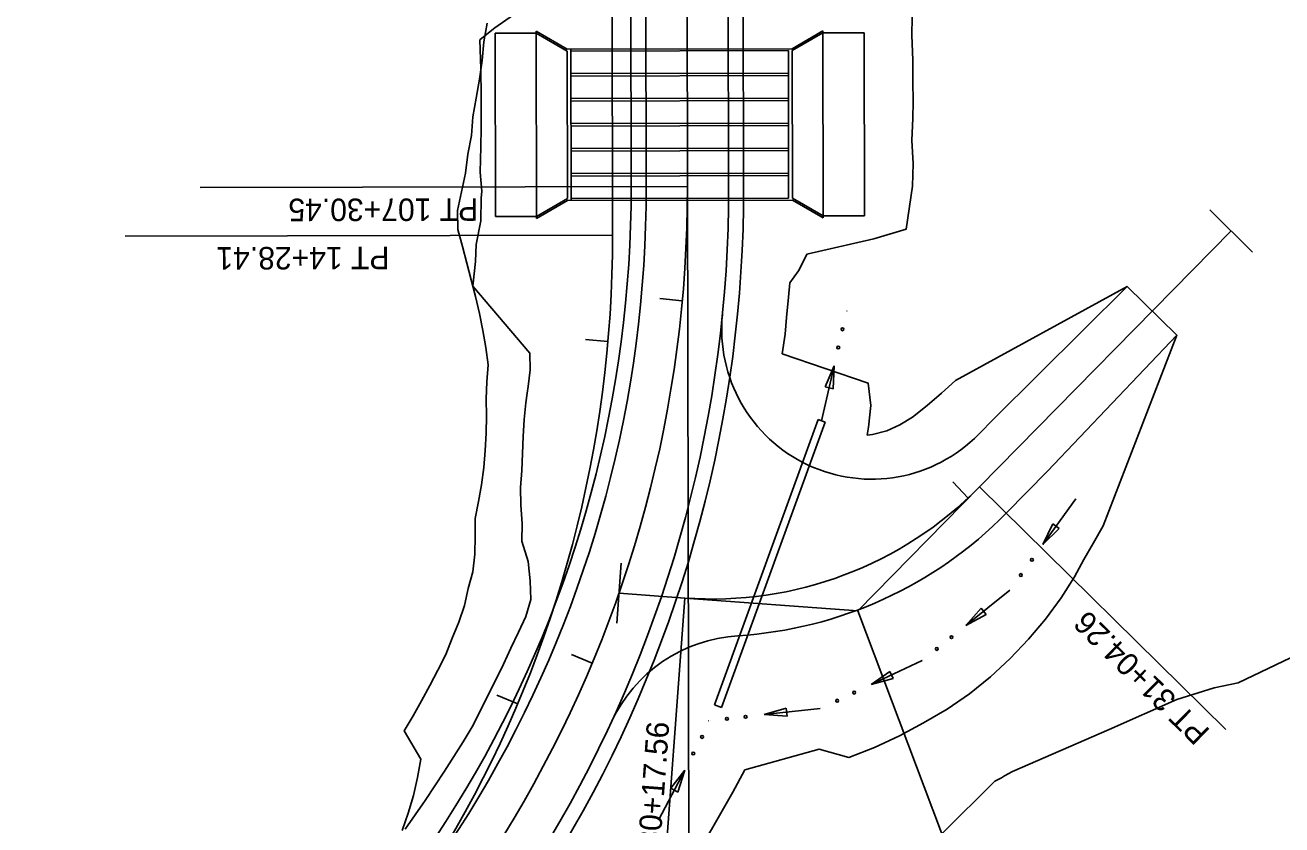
# Model space of a CAD drawing. Extents: x 1395202 to 1465904, y 1787951 to 1846942.
# Drawn here: x 1405603.4 to 1405938.6, y 1842358 to 1842571.2 of the extents above; entities that cross this region are included whole.
import ezdxf

# ---------------------------------------------------------------- set-up
doc = ezdxf.new("R2010")
doc.units = 0
for name, color, linetype in [('R_Drainage', 7, 'Continuous'), ('R_Horiz Alg Tangents', 7, 'Continuous'), ('R_Horz Alg', 7, 'Continuous'), ('R_Horz Alg Annot', 7, 'Continuous'), ('R_Horz Alg Stationing', 7, 'Continuous'), ('R_Perimeter', 7, 'Continuous'), ('R_Proposed Lane', 7, 'Continuous'), ('R_Proposed Shoulder', 7, 'Continuous'), ('R_SFHA', 7, 'Continuous'), ('R_Special Ditch', 7, 'Continuous'), ('R_Temp Perimeter', 7, 'Continuous'), ('R_Temp_Horz Alg', 7, 'Continuous'), ('R_Temp_Horz Alg Annot', 7, 'Continuous'), ('R_Temp_Horz Alg Stationing', 7, 'Continuous')]:
    doc.layers.add(name, color=color, linetype=linetype)

msp = doc.modelspace()

# ---------------------------------------------------------------- linework, layer by layer
at = {"layer": 'R_Drainage'}
for p, q in [((1405728.78, 1842569.06), (1405739.78, 1842569.08)), ((1405728.86, 1842520.19), (1405728.78, 1842569.06)), ((1405739.78, 1842569.58), (1405748, 1842564.81)), ((1405739.78, 1842569.58), (1405739.78, 1842569.08)), ((1405739.78, 1842569.08), (1405748, 1842564.31)), ((1405739.78, 1842569.08), (1405739.86, 1842520.21)), ((1405808, 1842564.93), (1405816.24, 1842569.67)), ((1405808, 1842564.43), (1405816.24, 1842569.17)), ((1405816.24, 1842569.67), (1405816.24, 1842569.17)), ((1405816.24, 1842569.17), (1405827.24, 1842569.19)), ((1405816.32, 1842520.37), (1405816.24, 1842569.17)), ((1405827.24, 1842569.19), (1405827.32, 1842520.39)), ((1405748, 1842564.81), (1405808, 1842564.93)), ((1405748, 1842564.31), (1405748.08, 1842524.98)), ((1405749.08, 1842524.48), (1405749, 1842564.81)), ((1405749, 1842564.31), (1405807, 1842564.43)), ((1405807, 1842564.43), (1405807.08, 1842525.1)), ((1405808, 1842564.43), (1405808.08, 1842525.1)), ((1405749.01, 1842558.31), (1405807.01, 1842558.43)), ((1405749.02, 1842557.65), (1405807.01, 1842557.77)), ((1405749.03, 1842551.65), (1405807.03, 1842551.77)), ((1405749.03, 1842550.98), (1405807.03, 1842551.1)), ((1405749.04, 1842544.98), (1405807.04, 1842545.1)), ((1405749.04, 1842544.31), (1405807.04, 1842544.43)), ((1405749.05, 1842538.31), (1405807.05, 1842538.43)), ((1405749.06, 1842537.65), (1405807.06, 1842537.77)), ((1405749.07, 1842531.65), (1405807.07, 1842531.77)), ((1405749.07, 1842530.98), (1405807.07, 1842531.1)), ((1405739.86, 1842520.21), (1405748.08, 1842524.98)), ((1405749.08, 1842524.98), (1405807.08, 1842525.1)), ((1405808.08, 1842525.1), (1405816.32, 1842520.37)), ((1405739.87, 1842519.71), (1405748.08, 1842524.48)), ((1405748.08, 1842524.48), (1405808.08, 1842524.6)), ((1405808.08, 1842524.6), (1405816.32, 1842519.87)), ((1405739.86, 1842520.21), (1405728.86, 1842520.19)), ((1405739.87, 1842519.71), (1405739.86, 1842520.21)), ((1405827.32, 1842520.39), (1405816.32, 1842520.37)), ((1405816.32, 1842519.87), (1405816.32, 1842520.37)), ((1405787.26, 1842389.96), (1405814.97, 1842466.07)), ((1405816.85, 1842465.38), (1405789.14, 1842389.27)), ((1405814.97, 1842466.07), (1405816.85, 1842465.38)), ((1405787.26, 1842389.96), (1405789.14, 1842389.27))]:
    msp.add_line(p, q, dxfattribs=at)
at = {"layer": 'R_Horiz Alg Tangents'}
for p, q in [((1405780.46, 1842339.07), (1405780.08, 1842528.16)), ((1405825.52, 1842415.08), (1405857.98, 1842448.08)), ((1405779.36, 1842418.47), (1405825.52, 1842415.08))]:
    msp.add_line(p, q, dxfattribs=at)
at = {"layer": 'R_Horz Alg'}
for p, q in [((1405780.08, 1842528.16), (1405779.12, 1842997.71)), ((1405780.08, 1842528.16), (1405779.12, 1842997.71)), ((1405857.98, 1842448.08), (1405925.1, 1842516.34)), ((1405761.84, 1842419.76), (1405779.36, 1842418.47))]:
    msp.add_line(p, q, dxfattribs=at)
for centre, radius, start, end in [((1405452.67, 1842527.5), 327.4, 300.1, 0.1167), ((1405452.67, 1842527.5), 327.4, 300.1, 0.1167), ((1405786.68, 1842518.2), 100, 265.8008, 315.4775)]:
    msp.add_arc(centre, radius, start, end, dxfattribs=at)
at = {"layer": 'R_Horz Alg Annot'}
msp.add_line((1405780.08, 1842528.16), (1405780.46, 1842339.07), dxfattribs=at)
for points in [[(1405780.08, 1842528.16), (1405650.08, 1842527.9)], [(1405923.71, 1842383.43), (1405857.98, 1842448.08)], [(1405773.28, 1842335.74), (1405779.36, 1842418.47)], [(1405825.52, 1842415.08), (1405867.82, 1842302.78)]]:
    msp.add_lwpolyline(points, dxfattribs=at)
at = {"layer": 'R_Horz Alg Stationing'}
for points in [[(1405919.4, 1842521.95), (1405930.81, 1842510.73)], [(1405919.4, 1842521.95), (1405930.81, 1842510.73)], [(1405772.75, 1842498.3), (1405778.72, 1842497.75)], [(1405850.83, 1842449.49), (1405854.92, 1842445.11)], [(1405762.43, 1842427.74), (1405761.26, 1842411.78)], [(1405749.15, 1842403.4), (1405754.69, 1842401.08)]]:
    msp.add_lwpolyline(points, dxfattribs=at)
at = {"layer": 'R_Perimeter'}
for points in [[(1405704.84, 1842356.85), (1405707.48, 1842360.67), (1405710.1, 1842364.52), (1405712.69, 1842368.39), (1405715.26, 1842372.28), (1405717.79, 1842376.2), (1405720.3, 1842380.14), (1405722.65, 1842384.17), (1405724.79, 1842388.32), (1405726.89, 1842392.49), (1405728.96, 1842396.67), (1405731, 1842400.88), (1405733.01, 1842405.09), (1405734.99, 1842409.33), (1405736.94, 1842413.58), (1405738.32, 1842418.06), (1405738.16, 1842423.09), (1405737.62, 1842428.2), (1405735.94, 1842433.61), (1405735.97, 1842438.38), (1405735.68, 1842443.2), (1405735.53, 1842447.92), (1405735.88, 1842452.47), (1405736.13, 1842457.02), (1405736.28, 1842461.56), (1405736.52, 1842466.06), (1405737.02, 1842470.48), (1405737.36, 1842473.08), (1405737.6, 1842474.88), (1405738.15, 1842479.28), (1405738.07, 1842483.76), (1405738.07, 1842483.76), (1405738.07, 1842483.76), (1405738.07, 1842483.76), (1405738.07, 1842483.76), (1405722.84, 1842501.66), (1405723.58, 1842508.22), (1405723.58, 1842508.22), (1405723.58, 1842508.22), (1405723.58, 1842508.22), (1405723.58, 1842508.22), (1405723.73, 1842512.73), (1405724.94, 1842519.05), (1405725.06, 1842525.05), (1405725.22, 1842526.95), (1405724.83, 1842532.01), (1405724.99, 1842538.75), (1405724.99, 1842539.03), (1405725.08, 1842543.47), (1405725.04, 1842547.56), (1405725.07, 1842552.28), (1405725.01, 1842559.6), (1405724.75, 1842567.34), (1405724.81, 1842567.43), (1405728.74, 1842570.53), (1405733.71, 1842573.99)], [(1405840.05, 1842573.34), (1405839.93, 1842568.52), (1405840.18, 1842561.91), (1405840.18, 1842555.94), (1405840.25, 1842551.13), (1405840.31, 1842550.85), (1405840.18, 1842546.4), (1405839.93, 1842540.43), (1405840.31, 1842534.33), (1405840.08, 1842528.29), (1405838.4, 1842516.8), (1405829.84, 1842514.28), (1405811.9, 1842510.13), (1405811.9, 1842510.09), (1405809.7, 1842505.73), (1405807.37, 1842502.53), (1405807.01, 1842498.69), (1405806.49, 1842493.26), (1405806.11, 1842488.87), (1405805.36, 1842483.61), (1405828.25, 1842475.8), (1405829.03, 1842469.82), (1405828.4, 1842464.03), (1405828.04, 1842461.89)], [(1405828.04, 1842461.89), (1405829.44, 1842462.08), (1405833.24, 1842463.05), (1405836.72, 1842464.61), (1405840.1, 1842466.7), (1405844.03, 1842469.84), (1405847.86, 1842473.09), (1405851.55, 1842476.48), (1405897.35, 1842501.55), (1405910.61, 1842488.52), (1405890.96, 1842437.71), (1405888.39, 1842433.23), (1405885.85, 1842428.71), (1405883.36, 1842424.15), (1405879.73, 1842418.53), (1405875.58, 1842412.88), (1405871.05, 1842407.47), (1405866.14, 1842402.33), (1405860.89, 1842397.45), (1405855.29, 1842392.93), (1405849.32, 1842388.88), (1405843.07, 1842385.22), (1405836.65, 1842381.76), (1405830.02, 1842378.64), (1405823.16, 1842375.97), (1405815.21, 1842378.21), (1405795.43, 1842372.67)], [(1405795.43, 1842372.67), (1405792.23, 1842366.72), (1405789.39, 1842361.72), (1405786.53, 1842356.75), (1405783.6, 1842351.82), (1405780.37, 1842347.06), (1405776.85, 1842342.5), (1405773.55, 1842337.82), (1405770.06, 1842333.29), (1405766.44, 1842328.85), (1405762.82, 1842324.45), (1405759.31, 1842319.99), (1405756.04, 1842315.37), (1405752.92, 1842310.65), (1405754.04, 1842302.76), (1405750.24, 1842298.44), (1405746.69, 1842293.94), (1405743.16, 1842289.42), (1405738.65, 1842285.06)]]:
    msp.add_lwpolyline(points, dxfattribs=at)
at = {"layer": 'R_Proposed Lane'}
for p, q in [((1405769.08, 1842528.24), (1405768.53, 1842797.69)), ((1405791.07, 1842528.28), (1405790.53, 1842797.73)), ((1405897.35, 1842501.55), (1405861.88, 1842466.31)), ((1405910.61, 1842488.52), (1405876.14, 1842452.29)), ((1405861.88, 1842466.31), (1405857.75, 1842462.11)), ((1405876.14, 1842452.29), (1405865.11, 1842441.07))]:
    msp.add_line(p, q, dxfattribs=at)
for centre, radius, start, end in [((1405452.67, 1842527.5), 316.4, 300.1, 0.1338), ((1405452.67, 1842527.5), 338.4, 300.1, 0.1338), ((1405829.23, 1842490.16), 40, 174.3376, 315.4775), ((1405786.68, 1842518.2), 110, 273.5817, 315.4775), ((1405796.05, 1842368.5), 40, 93.5817, 155.1535)]:
    msp.add_arc(centre, radius, start, end, dxfattribs=at)
at = {"layer": 'R_Proposed Shoulder'}
for p, q in [((1405765.08, 1842528.23), (1405764.53, 1842797.68)), ((1405795.07, 1842528.29), (1405794.53, 1842797.74))]:
    msp.add_line(p, q, dxfattribs=at)
for radius in [312.4, 342.4]:
    msp.add_arc((1405452.67, 1842527.5), radius, 300.1, 0.1338, dxfattribs=at)
at = {"layer": 'R_SFHA'}
msp.add_lwpolyline([(1405942.98, 1842403.54), (1405926.95, 1842395.84), (1405920.59, 1842394.5), (1405910.58, 1842391.39), (1405892.6, 1842383.39), (1405866.75, 1842372.19), (1405864.61, 1842371.04), (1405863.87, 1842370.51), (1405862.03, 1842369.6), (1405848.1, 1842355.77)], dxfattribs=at)
at = {"layer": 'R_Special Ditch'}
for p, q in [((1405822.59, 1842494.98), (1405822.6, 1842495.01)), ((1405819.24, 1842480.36), (1405815.88, 1842465.74)), ((1405819.24, 1842480.36), (1405816.86, 1842474.75)), ((1405818.93, 1842474.27), (1405819.24, 1842480.36)), ((1405816.86, 1842474.75), (1405818.93, 1842474.27)), ((1405874.86, 1842432.75), (1405883.64, 1842444.91)), ((1405877.52, 1842438.23), (1405874.86, 1842432.75)), ((1405879.23, 1842437), (1405877.52, 1842438.23)), ((1405874.86, 1842432.75), (1405879.23, 1842437)), ((1405854.38, 1842411.18), (1405866.08, 1842420.57)), ((1405866.09, 1842420.58), (1405866.07, 1842420.55)), ((1405858.4, 1842415.76), (1405854.38, 1842411.18)), ((1405859.72, 1842414.11), (1405858.4, 1842415.76)), ((1405854.38, 1842411.18), (1405859.72, 1842414.11)), ((1405829.09, 1842395.4), (1405842.66, 1842401.79)), ((1405842.67, 1842401.8), (1405842.64, 1842401.78)), ((1405834.07, 1842398.91), (1405829.09, 1842395.4)), ((1405834.97, 1842397), (1405834.07, 1842398.91)), ((1405829.09, 1842395.4), (1405834.97, 1842397)), ((1405806.44, 1842389.09), (1405800.59, 1842387.39)), ((1405800.59, 1842387.39), (1405815.5, 1842389.01)), ((1405800.59, 1842387.39), (1405806.66, 1842386.98)), ((1405806.66, 1842386.98), (1405806.44, 1842389.09)), ((1405815.52, 1842389.01), (1405815.48, 1842389)), ((1405785.67, 1842385.77), (1405785.64, 1842385.77)), ((1405786.33, 1842385.83), (1405786.35, 1842385.86)), ((1405779.36, 1842372.55), (1405772.38, 1842359.27)), ((1405779.36, 1842372.55), (1405775.63, 1842367.73)), ((1405777.5, 1842366.74), (1405779.36, 1842372.55)), ((1405775.63, 1842367.73), (1405777.5, 1842366.74)), ((1405772.47, 1842359.41), (1405772.49, 1842359.45))]:
    msp.add_line(p, q, dxfattribs=at)
for centre in [(1405821.44, 1842490.13), (1405820.32, 1842485.25), (1405871.97, 1842428.67), (1405869.03, 1842424.6), (1405850.49, 1842408.02), (1405846.58, 1842404.89), (1405820.04, 1842391.1), (1405824.57, 1842393.24), (1405790.63, 1842386.27), (1405795.61, 1842386.81), (1405783.98, 1842381.43), (1405781.65, 1842377)]:
    msp.add_circle(centre, 0.375, dxfattribs=at)
at = {"layer": 'R_Temp Perimeter'}
msp.add_lwpolyline([(1405703.97, 1842356.48), (1405705.64, 1842361.07), (1405707.01, 1842365.8), (1405708.13, 1842370.63), (1405709, 1842375.54), (1405704.5, 1842383.08), (1405706.89, 1842387.06), (1405709.2, 1842391.07), (1405711.39, 1842395.17), (1405713.55, 1842399.28), (1405715.61, 1842403.45), (1405717.35, 1842407.75), (1405719.12, 1842412.05), (1405720.64, 1842416.44), (1405721.59, 1842421.02), (1405722.81, 1842425.49), (1405723.35, 1842430.16), (1405723.45, 1842434.93), (1405723.49, 1842439.68), (1405724.38, 1842444.18), (1405725.16, 1842448.69), (1405725.76, 1842453.24), (1405726.18, 1842457.81), (1405726.44, 1842462.39), (1405726.52, 1842466.99), (1405726.42, 1842471.59), (1405726.59, 1842476.13), (1405726.95, 1842480.63), (1405726.34, 1842485.23), (1405725.53, 1842489.81), (1405724.6, 1842494.36), (1405723.55, 1842498.88), (1405722.41, 1842503.36), (1405721.26, 1842507.8), (1405720.08, 1842512.21), (1405718.86, 1842516.77), (1405718.76, 1842521.77), (1405719.83, 1842526.78), (1405720.86, 1842531.78), (1405721.47, 1842536.78), (1405722.51, 1842541.78), (1405722.88, 1842546.78), (1405723.72, 1842551.78), (1405724.62, 1842556.79), (1405725.31, 1842561.79), (1405725.8, 1842566.79), (1405726.66, 1842571.79)], dxfattribs=at)
at = {"layer": 'R_Temp_Horz Alg'}
msp.add_line((1405760.1, 1842515.27), (1405759.91, 1842611.3), dxfattribs=at)
msp.add_arc((1405441.79, 1842514.62), 318.31, 300.5194, 0.1167, dxfattribs=at)
at = {"layer": 'R_Temp_Horz Alg Annot'}
msp.add_lwpolyline([(1405760.1, 1842515.27), (1405630.1, 1842515)], dxfattribs=at)
at = {"layer": 'R_Temp_Horz Alg Stationing'}
for points in [[(1405752.92, 1842487.42), (1405758.89, 1842486.89)], [(1405729.28, 1842392.61), (1405734.81, 1842390.26)]]:
    msp.add_lwpolyline(points, dxfattribs=at)

# ---------------------------------------------------------------- texts
at = {"layer": 'R_Horz Alg Annot'}
for s, rotation, p in [('PT 107+30.45', 180.1167, (1405724.28, 1842525.05)), ('PT 31+04.26', 135.4775, (1405919.75, 1842383.13)), ('PC 30+17.56', 85.8008, (1405771.83, 1842338.37))]:
    msp.add_text(s, height=6, rotation=rotation, dxfattribs=at).set_placement(p)
at = {"layer": 'R_Temp_Horz Alg Annot'}
msp.add_text('PT 14+28.41', height=6, rotation=180.1167, dxfattribs=at).set_placement((1405700.6, 1842512.14))

doc.saveas('drawing.dxf')
